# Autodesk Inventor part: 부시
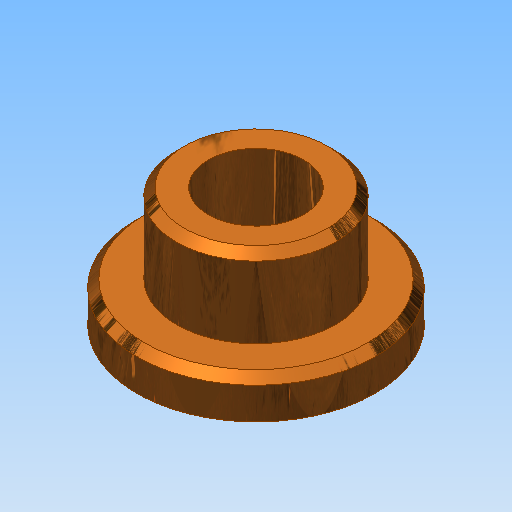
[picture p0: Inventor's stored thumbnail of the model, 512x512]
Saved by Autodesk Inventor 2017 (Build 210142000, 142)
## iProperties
Created: 2016-02
Part Number: 부시
Material: 스테인리스강
Document SubType Name: Modeling
Designer: mduedu
Density: 8.08 g/cm^3
Appearance: 금속 1600F 열
Mass: 39.4553 g
Surface Area: 27.3717 cm^2
Volume: 4.88308 cm^3
Author: mduedu
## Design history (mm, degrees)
sketch "스케치1"
  geometry: C1 r 15 at (0, 0); 1 further point
  constraints: 1 centre point, 1 coincident
  dimensions: "d0" = 30 diameter of C1
extrude "돌출1" new body sketch "스케치1" distance "d1" = 5; taper "d2" = 0 deg
sketch "스케치2"
  geometry: C1 r 10 at (0, 0); 1 further point
  constraints: 1 centre point, 1 coincident
  dimensions: "d3" = 20 diameter of C1
extrude "돌출2" join sketch "스케치2" distance "d4" = 10; taper "d5" = 0 deg
hole "구멍1" diameter "d8" = 12; stored, may be unused: countersink angle "d12" = 90 deg, drill point angle "d14" = 118 deg; dims "d9" = 6, "d10" = 4, "d11" = 2, "d13" = 8, "d15" = 10, "d16" = 10
chamfer "모따기1" distance "d17" = 1; stored, may be unused: second distance "d18" = 2, angle "d19" = 45 deg
chamfer "모따기2" distance "d20" = 1; stored, may be unused: second distance "d21" = 2, angle "d22" = 45 deg
chamfer "모따기3" distance "d23" = 1; stored, may be unused: second distance "d24" = 2, angle "d25" = 45 deg
node "솔리드1"
